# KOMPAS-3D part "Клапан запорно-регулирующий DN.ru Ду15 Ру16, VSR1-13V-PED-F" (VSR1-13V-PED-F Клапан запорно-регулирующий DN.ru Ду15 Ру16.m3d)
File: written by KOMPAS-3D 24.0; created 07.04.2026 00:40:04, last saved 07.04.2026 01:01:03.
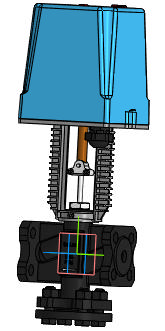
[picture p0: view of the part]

Document properties: Автор: R2D2; Полное имя файла: VSR1-13V-PED-F Клапан запорно-регулирующий DN.ru Ду15 Ру16.cdw

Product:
- Part/product: Клапан запорно-регулирующий DN.ru Ду15 Ру16  | designation VSR1-13V-PED-F
    Масса: 6.1
    Раздел спецификации: Прочие изделия
    Форматы листов документа: A3
    Примечание: D090-02880

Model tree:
1. Операция без истории:1  (labels: SHAPEOBJECT3D_ATTR_BUTT)

Expressions: VSR1-13V-PED-F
